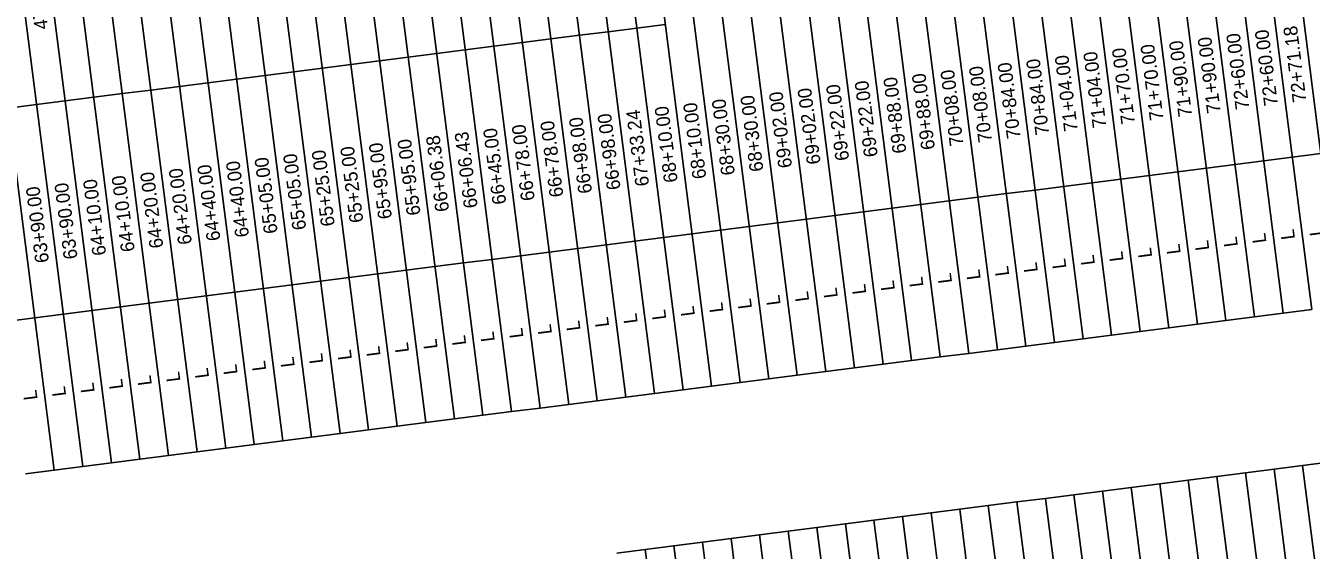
# Model space of a CAD drawing. Extents: x 2364621 to 2374814, y 792603 to 806745.
# Drawn here: x 2369200 to 2371409, y 803235 to 804137 of the extents above; entities that cross this region are included whole.
import ezdxf

# ---------------------------------------------------------------- set-up
doc = ezdxf.new("R2010")
doc.units = 0
doc.layers.add('CTL Sheet Table Cell', color=7, linetype='Continuous')
doc.layers.add('CTL Sheet Text', color=7, linetype='Continuous')

msp = doc.modelspace()

# ---------------------------------------------------------------- linework, layer by layer
at = {"layer": 'CTL Sheet Table Cell'}
for p, q in [((2371410.2, 803648.7), (2371176, 805482.5)), ((2371459.3, 803655), (2371225.1, 805488.7)), ((2371213.7, 803623.6), (2370979.5, 805457.4)), ((2371262.8, 803629.9), (2371028.6, 805463.6)), ((2371311.9, 803636.2), (2371077.7, 805469.9)), ((2371361, 803642.5), (2371126.8, 805476.2)), ((2371066.3, 803604.8), (2370832.1, 805438.5)), ((2371115.4, 803611.1), (2370881.2, 805444.8)), ((2371164.6, 803617.4), (2370930.4, 805451.1)), ((2370869.9, 803579.7), (2370635.7, 805413.5)), ((2370919, 803586), (2370684.8, 805419.7)), ((2370968.1, 803592.3), (2370733.9, 805426)), ((2371017.2, 803598.5), (2370783, 805432.3)), ((2370722.5, 803560.9), (2370488.3, 805394.6)), ((2370771.6, 803567.2), (2370537.4, 805400.9)), ((2370820.7, 803573.4), (2370586.5, 805407.2)), ((2370526, 803535.8), (2370291.8, 805369.5)), ((2370575.1, 803542.1), (2370340.9, 805375.8)), ((2370624.3, 803548.4), (2370390.1, 805382.1)), ((2370673.4, 803554.6), (2370439.2, 805388.4)), ((2370329.6, 803510.7), (2370095.4, 805344.4)), ((2370378.7, 803517), (2370144.5, 805350.7)), ((2370427.8, 803523.3), (2370193.6, 805357)), ((2370476.9, 803529.5), (2370242.7, 805363.3)), ((2370182.2, 803491.9), (2369948, 805325.6)), ((2370231.3, 803498.2), (2369997.1, 805331.9)), ((2370280.4, 803504.4), (2370046.2, 805338.2)), ((2369985.7, 803466.8), (2369751.5, 805300.5)), ((2370034.9, 803473.1), (2369800.6, 805306.8)), ((2370084, 803479.3), (2369849.8, 805313.1)), ((2370133.1, 803485.6), (2369898.9, 805319.4)), ((2369838.4, 803448), (2369604.2, 805281.7)), ((2369887.5, 803454.3), (2369653.3, 805288)), ((2369936.6, 803460.5), (2369702.4, 805294.3)), ((2369641.9, 803422.9), (2369407.7, 805256.6)), ((2369691, 803429.2), (2369456.8, 805262.9)), ((2369740.1, 803435.4), (2369505.9, 805269.2)), ((2369789.3, 803441.7), (2369555.1, 805275.4)), ((2369494.6, 803404.1), (2369260.4, 805237.8)), ((2369543.7, 803410.3), (2369309.5, 805244.1)), ((2369592.8, 803416.6), (2369358.6, 805250.3)), ((2369298.1, 803379), (2369063.9, 805212.7)), ((2369347.2, 803385.2), (2369113, 805219)), ((2369396.3, 803391.5), (2369162.1, 805225.3)), ((2369445.4, 803397.8), (2369211.2, 805231.5)), ((2369249, 803372.7), (2369014.8, 805206.4)), ((2370201, 804126.6), (2370250.1, 804132.9)), ((2370250.1, 804132.9), (2370299.2, 804139.1)), ((2370004.5, 804101.5), (2370053.6, 804107.8)), ((2370053.6, 804107.8), (2370102.7, 804114.1)), ((2370102.7, 804114.1), (2370151.9, 804120.3)), ((2370151.9, 804120.3), (2370201, 804126.6)), ((2369857.2, 804082.7), (2369906.3, 804089)), ((2369906.3, 804089), (2369955.4, 804095.2)), ((2369955.4, 804095.2), (2370004.5, 804101.5)), ((2369660.7, 804057.6), (2369709.8, 804063.9)), ((2369709.8, 804063.9), (2369758.9, 804070.1)), ((2369758.9, 804070.1), (2369808, 804076.4)), ((2369808, 804076.4), (2369857.2, 804082.7)), ((2369513.3, 804038.8), (2369562.4, 804045)), ((2369562.4, 804045), (2369611.6, 804051.3)), ((2369611.6, 804051.3), (2369660.7, 804057.6)), ((2369316.9, 804013.7), (2369366, 804020)), ((2369366, 804020), (2369415.1, 804026.2)), ((2369415.1, 804026.2), (2369464.2, 804032.5)), ((2369464.2, 804032.5), (2369513.3, 804038.8)), ((2369169.5, 803994.9), (2369218.6, 804001.1)), ((2369218.6, 804001.1), (2369267.7, 804007.4)), ((2369267.7, 804007.4), (2369316.9, 804013.7)), ((2371327.6, 803904.4), (2371376.7, 803910.7)), ((2371376.7, 803910.7), (2371425.8, 803917)), ((2371180.2, 803885.6), (2371229.3, 803891.9)), ((2371229.3, 803891.9), (2371278.5, 803898.1)), ((2371278.5, 803898.1), (2371327.6, 803904.4)), ((2370983.8, 803860.5), (2371032.9, 803866.8)), ((2371032.9, 803866.8), (2371082, 803873)), ((2371082, 803873), (2371131.1, 803879.3)), ((2371131.1, 803879.3), (2371180.2, 803885.6)), ((2370836.4, 803841.7), (2370885.5, 803848)), ((2370885.5, 803848), (2370934.6, 803854.2)), ((2370934.6, 803854.2), (2370983.8, 803860.5)), ((2370639.9, 803816.6), (2370689, 803822.9)), ((2370689, 803822.9), (2370738.2, 803829.1)), ((2370738.2, 803829.1), (2370787.3, 803835.4)), ((2370787.3, 803835.4), (2370836.4, 803841.7)), ((2370443.5, 803791.5), (2370492.6, 803797.8)), ((2370492.6, 803797.8), (2370541.7, 803804)), ((2370541.7, 803804), (2370590.8, 803810.3)), ((2370590.8, 803810.3), (2370639.9, 803816.6)), ((2370296.1, 803772.7), (2370345.2, 803778.9)), ((2370345.2, 803778.9), (2370394.3, 803785.2)), ((2370394.3, 803785.2), (2370443.5, 803791.5)), ((2370099.6, 803747.6), (2370148.7, 803753.9)), ((2370148.7, 803753.9), (2370197.9, 803760.1)), ((2370197.9, 803760.1), (2370247, 803766.4)), ((2370247, 803766.4), (2370296.1, 803772.7)), ((2369952.3, 803728.8), (2370001.4, 803735)), ((2370001.4, 803735), (2370050.5, 803741.3)), ((2370050.5, 803741.3), (2370099.6, 803747.6)), ((2369755.8, 803703.7), (2369804.9, 803709.9)), ((2369804.9, 803709.9), (2369854, 803716.2)), ((2369854, 803716.2), (2369903.2, 803722.5)), ((2369903.2, 803722.5), (2369952.3, 803728.8)), ((2369608.5, 803684.8), (2369657.6, 803691.1)), ((2369657.6, 803691.1), (2369706.7, 803697.4)), ((2369706.7, 803697.4), (2369755.8, 803703.7)), ((2369412, 803659.8), (2369461.1, 803666)), ((2369461.1, 803666), (2369510.2, 803672.3)), ((2369510.2, 803672.3), (2369559.3, 803678.6)), ((2369559.3, 803678.6), (2369608.5, 803684.8)), ((2369264.6, 803640.9), (2369313.7, 803647.2)), ((2369313.7, 803647.2), (2369362.9, 803653.5)), ((2369362.9, 803653.5), (2369412, 803659.8)), ((2371361, 803642.5), (2371410.2, 803648.7)), ((2369166.4, 803628.4), (2369215.5, 803634.7)), ((2369215.5, 803634.7), (2369264.6, 803640.9)), ((2371164.6, 803617.4), (2371213.7, 803623.6)), ((2371213.7, 803623.6), (2371262.8, 803629.9)), ((2371262.8, 803629.9), (2371311.9, 803636.2)), ((2371311.9, 803636.2), (2371361, 803642.5)), ((2371017.2, 803598.5), (2371066.3, 803604.8)), ((2371066.3, 803604.8), (2371115.4, 803611.1)), ((2371115.4, 803611.1), (2371164.6, 803617.4)), ((2370820.7, 803573.4), (2370869.9, 803579.7)), ((2370869.9, 803579.7), (2370919, 803586)), ((2370919, 803586), (2370968.1, 803592.3)), ((2370968.1, 803592.3), (2371017.2, 803598.5)), ((2370624.3, 803548.4), (2370673.4, 803554.6)), ((2370673.4, 803554.6), (2370722.5, 803560.9)), ((2370722.5, 803560.9), (2370771.6, 803567.2)), ((2370771.6, 803567.2), (2370820.7, 803573.4)), ((2370476.9, 803529.5), (2370526, 803535.8)), ((2370526, 803535.8), (2370575.1, 803542.1)), ((2370575.1, 803542.1), (2370624.3, 803548.4)), ((2370280.4, 803504.4), (2370329.6, 803510.7)), ((2370329.6, 803510.7), (2370378.7, 803517)), ((2370378.7, 803517), (2370427.8, 803523.3)), ((2370427.8, 803523.3), (2370476.9, 803529.5)), ((2370133.1, 803485.6), (2370182.2, 803491.9)), ((2370182.2, 803491.9), (2370231.3, 803498.2)), ((2370231.3, 803498.2), (2370280.4, 803504.4)), ((2369936.6, 803460.5), (2369985.7, 803466.8)), ((2369985.7, 803466.8), (2370034.9, 803473.1)), ((2370034.9, 803473.1), (2370084, 803479.3)), ((2370084, 803479.3), (2370133.1, 803485.6)), ((2369789.3, 803441.7), (2369838.4, 803448)), ((2369838.4, 803448), (2369887.5, 803454.3)), ((2369887.5, 803454.3), (2369936.6, 803460.5)), ((2369592.8, 803416.6), (2369641.9, 803422.9)), ((2369641.9, 803422.9), (2369691, 803429.2)), ((2369691, 803429.2), (2369740.1, 803435.4)), ((2369740.1, 803435.4), (2369789.3, 803441.7)), ((2369445.4, 803397.8), (2369494.6, 803404.1)), ((2369494.6, 803404.1), (2369543.7, 803410.3)), ((2369543.7, 803410.3), (2369592.8, 803416.6)), ((2369249, 803372.7), (2369298.1, 803379)), ((2369298.1, 803379), (2369347.2, 803385.2)), ((2369347.2, 803385.2), (2369396.3, 803391.5)), ((2369396.3, 803391.5), (2369445.4, 803397.8)), ((2371345.4, 803374.2), (2371394.5, 803380.5)), ((2371394.5, 803380.5), (2371443.6, 803386.8)), ((2371628.7, 801546.8), (2371394.5, 803380.5)), ((2369199.8, 803366.4), (2369249, 803372.7)), ((2371198, 803355.4), (2371247.1, 803361.7)), ((2371247.1, 803361.7), (2371296.3, 803367.9)), ((2371481.3, 801527.9), (2371247.1, 803361.7)), ((2371296.3, 803367.9), (2371345.4, 803374.2)), ((2371530.5, 801534.2), (2371296.3, 803367.9)), ((2371579.6, 801540.5), (2371345.4, 803374.2)), ((2371001.5, 803330.3), (2371050.7, 803336.6)), ((2371050.7, 803336.6), (2371099.8, 803342.8)), ((2371284.9, 801502.8), (2371050.7, 803336.6)), ((2371099.8, 803342.8), (2371148.9, 803349.1)), ((2371334, 801509.1), (2371099.8, 803342.8)), ((2371148.9, 803349.1), (2371198, 803355.4)), ((2371383.1, 801515.4), (2371148.9, 803349.1)), ((2371432.2, 801521.7), (2371198, 803355.4)), ((2370854.2, 803311.5), (2370903.3, 803317.8)), ((2370903.3, 803317.8), (2370952.4, 803324)), ((2371137.5, 801484), (2370903.3, 803317.8)), ((2370952.4, 803324), (2371001.5, 803330.3)), ((2371186.6, 801490.3), (2370952.4, 803324)), ((2371235.8, 801496.6), (2371001.5, 803330.3)), ((2370657.7, 803286.4), (2370706.8, 803292.7)), ((2370706.8, 803292.7), (2370756, 803298.9)), ((2370941, 801458.9), (2370706.8, 803292.7)), ((2370756, 803298.9), (2370805.1, 803305.2)), ((2370990.2, 801465.2), (2370756, 803298.9)), ((2370805.1, 803305.2), (2370854.2, 803311.5)), ((2371039.3, 801471.5), (2370805.1, 803305.2)), ((2371088.4, 801477.7), (2370854.2, 803311.5)), ((2370461.3, 803261.3), (2370510.4, 803267.6)), ((2370510.4, 803267.6), (2370559.5, 803273.8)), ((2370744.6, 801433.8), (2370510.4, 803267.6)), ((2370559.5, 803273.8), (2370608.6, 803280.1)), ((2370793.7, 801440.1), (2370559.5, 803273.8)), ((2370608.6, 803280.1), (2370657.7, 803286.4)), ((2370842.8, 801446.4), (2370608.6, 803280.1)), ((2370891.9, 801452.7), (2370657.7, 803286.4)), ((2370313.9, 803242.5), (2370363, 803248.8)), ((2370363, 803248.8), (2370412.1, 803255)), ((2370597.2, 801415), (2370363, 803248.8)), ((2370412.1, 803255), (2370461.3, 803261.3)), ((2370646.3, 801421.3), (2370412.1, 803255)), ((2370695.5, 801427.6), (2370461.3, 803261.3)), ((2370215.7, 803229.9), (2370264.8, 803236.2)), ((2370264.8, 803236.2), (2370313.9, 803242.5)), ((2370499, 801402.5), (2370264.8, 803236.2)), ((2370548.1, 801408.7), (2370313.9, 803242.5))]:
    msp.add_line(p, q, dxfattribs=at)

# ---------------------------------------------------------------- texts
at = {"layer": 'CTL Sheet Text'}
for s, height, p in [('47.00', 23.58, (2369238.8, 804131.7)), ('72+60.00', 23.58, (2371352.2, 804000.2)), ('72+71.18', 23.58, (2371401.3, 804006.5)), ('71+90.00', 23.58, (2371204.8, 803981.4)), ('71+90.00', 23.58, (2371254, 803987.6)), ('72+60.00', 23.58, (2371303.1, 803993.9)), ('71+04.00', 23.58, (2371008.4, 803956.3)), ('71+04.00', 23.58, (2371057.5, 803962.5)), ('71+70.00', 23.58, (2371106.6, 803968.8)), ('71+70.00', 23.58, (2371155.7, 803975.1)), ('70+08.00', 23.58, (2370861, 803937.5)), ('70+84.00', 23.58, (2370910.1, 803943.7)), ('70+84.00', 23.58, (2370959.2, 803950)), ('69+22.00', 23.58, (2370664.5, 803912.4)), ('69+88.00', 23.58, (2370713.7, 803918.6)), ('69+88.00', 23.58, (2370762.8, 803924.9)), ('70+08.00', 23.58, (2370811.9, 803931.2)), ('69+02.00', 23.58, (2370517.2, 803893.5)), ('69+02.00', 23.58, (2370566.3, 803899.8)), ('69+22.00', 23.58, (2370615.4, 803906.1)), ('68+10.00', 23.58, (2370320.7, 803868.5)), ('68+10.00', 23.58, (2370369.8, 803874.7)), ('68+30.00', 23.58, (2370419, 803881)), ('68+30.00', 23.58, (2370468.1, 803887.3)), ('66+98.00', 23.58, (2370173.4, 803849.6)), ('66+98.00', 23.58, (2370222.5, 803855.9)), ('67+33.24', 23.58, (2370271.6, 803862.2)), ('66+06.43', 23.58, (2369976.9, 803824.5)), ('66+45.00', 23.58, (2370026, 803830.8)), ('66+78.00', 23.58, (2370075.1, 803837.1)), ('66+78.00', 23.58, (2370124.2, 803843.4)), ('65+95.00', 23.58, (2369829.5, 803805.7)), ('65+95.00', 23.58, (2369878.7, 803812)), ('66+06.38', 23.58, (2369927.8, 803818.3)), ('65+05.00', 23.58, (2369633.1, 803780.6)), ('65+05.00', 23.58, (2369682.2, 803786.9)), ('65+25.00', 23.58, (2369731.3, 803793.2)), ('65+25.00', 23.58, (2369780.4, 803799.4)), ('64+20.00', 23.58, (2369485.7, 803761.8)), ('64+40.00', 23.58, (2369534.8, 803768.1)), ('64+40.00', 23.58, (2369583.9, 803774.4)), ('63+90.00', 23.58, (2369289.2, 803736.7)), ('64+10.00', 23.58, (2369338.4, 803743)), ('64+10.00', 23.58, (2369387.5, 803749.3)), ('64+20.00', 23.58, (2369436.6, 803755.5)), ('63+90.00', 23.58, (2369240.1, 803730.4)), ('L', 23.6, (2371332.4, 803764.1)), ('L', 23.6, (2371381.5, 803770.3)), ('L', 23.6, (2371430.7, 803776.6)), ('L', 23.6, (2371136, 803739)), ('L', 23.6, (2371185.1, 803745.2)), ('L', 23.6, (2371234.2, 803751.5)), ('L', 23.6, (2371283.3, 803757.8)), ('L', 23.6, (2370988.6, 803720.1)), ('L', 23.6, (2371037.7, 803726.4)), ('L', 23.6, (2371086.8, 803732.7)), ('L', 23.6, (2370792.1, 803695)), ('L', 23.6, (2370841.3, 803701.3)), ('L', 23.6, (2370890.4, 803707.6)), ('L', 23.6, (2370939.5, 803713.9)), ('L', 23.6, (2370644.8, 803676.2)), ('L', 23.6, (2370693.9, 803682.5)), ('L', 23.6, (2370743, 803688.8)), ('L', 23.6, (2370448.3, 803651.1)), ('L', 23.6, (2370497.4, 803657.4)), ('L', 23.6, (2370546.5, 803663.7)), ('L', 23.6, (2370595.7, 803670)), ('L', 23.6, (2370301, 803632.3)), ('L', 23.6, (2370350.1, 803638.6)), ('L', 23.6, (2370399.2, 803644.9)), ('L', 23.6, (2370104.5, 803607.2)), ('L', 23.6, (2370153.6, 803613.5)), ('L', 23.6, (2370202.7, 803619.8)), ('L', 23.6, (2370251.8, 803626)), ('L', 23.6, (2369957.1, 803588.4)), ('L', 23.6, (2370006.2, 803594.7)), ('L', 23.6, (2370055.4, 803600.9)), ('L', 23.6, (2369760.7, 803563.3)), ('L', 23.6, (2369809.8, 803569.6)), ('L', 23.6, (2369858.9, 803575.9)), ('L', 23.6, (2369908, 803582.1)), ('L', 23.6, (2369613.3, 803544.5)), ('L', 23.6, (2369662.4, 803550.8)), ('L', 23.6, (2369711.5, 803557)), ('L', 23.6, (2369416.8, 803519.4)), ('L', 23.6, (2369465.9, 803525.7)), ('L', 23.6, (2369515.1, 803531.9)), ('L', 23.6, (2369564.2, 803538.2)), ('L', 23.6, (2369220.4, 803494.3)), ('L', 23.6, (2369269.5, 803500.6)), ('L', 23.6, (2369318.6, 803506.8)), ('L', 23.6, (2369367.7, 803513.1))]:
    msp.add_text(s, height=height, rotation=97.2784, dxfattribs=at).set_placement(p)

doc.saveas('drawing.dxf')
